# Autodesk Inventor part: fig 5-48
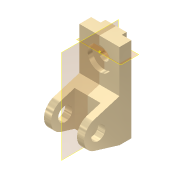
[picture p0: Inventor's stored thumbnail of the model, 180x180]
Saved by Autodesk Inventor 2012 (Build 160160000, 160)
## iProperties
Shininess: 65.0
Angle Display Precision: 2
Document Length Units: 11269
Document Angle Units: 11279
Document Time Units: 11290
Document Mass Units: 11283
Document Length Units Precision: 3
Document Angle Units Precision: 2
Created: 2001-11
Part Number: fig 5-48
Document SubType Name: Modeling
Designer: Renu Muthoo
Density: 1 g/cm^3
Material: Default
Density: 0.0
Volumn: 0.0
Area: 0.0
PropertySet Name: Model Information
Control State: 0
Master: False
Checked Out: False
Author: Renu Muthoo
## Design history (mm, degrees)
node "Sketch1"
sketch "Sketch2"
  geometry: L1 (33.257, 104.664)-(33.257, -75.336); L2 (33.257, -75.336)-(8.257, -75.336); L3 (8.257, -75.336)-(-45.451, -59.045); L4 (-45.451, -1.628)-(8.257, 14.664); L5 (8.257, 14.664)-(8.257, 104.664); L6 (8.257, 104.664)-(33.257, 104.664); C1 r 15 at (-36.743, -30.336); A1 r 30 centre (-36.743, -30.336) between (-45.451, -1.628) and (-45.451, -59.045)
  constraints: 12 end point, 2 centre point, 2 equal length, 2 parallel, 2 point on circle, 2 tangent, 1 coincident, 1 perpendicular, 1 vertical
  dimensions: "d0" = 180 distance of L1.start L1.end; "d1" = 30 radius of A1; "d2" = 25 distance of L5.end L1.start; "d3" = 45 distance from line of L2 A1.centre; "d4" = 70 distance from line of L1 A1.centre; "d5" = 30 diameter of C1
extrude "Extrusion1" new body sketch "Sketch2" distance "d6" = 85; taper "d7" = 0 deg
workplane "Work Plane1"
sketch "Sketch3"
  geometry: L1 (15, 62.364)-(70, 62.364); L2 (70, 62.364)-(70, -52.386); L3 (70, -52.386)-(15, -52.386); L4 (15, -52.386)-(15, 62.364); L5 (0, -45)-(0, -28.708) reference
  constraints: 8 end point, 2 parallel, 1 horizontal, 1 perpendicular
  dimensions: "d8" = 55 distance of L1.start L1.end; "d9" = 15 distance between parallel lines of L5 L4
extrude "Extrusion2" cut sketch "Sketch3" distance "d10" = 50; taper "d11" = 0 deg
sketch "Sketch4"
  geometry: L1 (0, 25)-(85, 25) reference; L2 (0, 0)-(0, 25) reference; L3 (20, 25)-(65, 25); L4 (65, 25)-(65, 35); L5 (65, 35)-(20, 35); L6 (20, 35)-(20, 25)
  constraints: 8 end point, 2 parallel, 1 horizontal, 1 perpendicular, 1 point on line
  dimensions: "d12" = 45 distance of L4.end L5.end; "d13" = 10 distance of L3.end L4.end; "d14" = 20 distance between parallel lines of L2 L6
extrude "Extrusion3" join sketch "Sketch4" stored distance "d15" = 50; taper "d16" = 0 deg
sketch "Sketch5"
  geometry: L1 (85, 0)-(85, 90) reference; L2 (0, 90)-(85, 90) reference; 1 further point
  dimensions: "d17" = 42 distance from line of L2 point (42.5, 48); "d18" = 42.5 distance from line of L1 point (42.5, 48)
hole "Hole1" sketch "Sketch5" at (42.5, 48) diameter "d19" = 20; stored, may be unused: countersink angle "d23" = 82 deg, drill point angle "d25" = 118 deg; dims "d20" = 6, "d21" = 50, "d22" = 10, "d24" = 8
workpoint "Work Point9"
  workplane "Work Plane8"
  workplane "Work Plane12"
body "Solid1"
